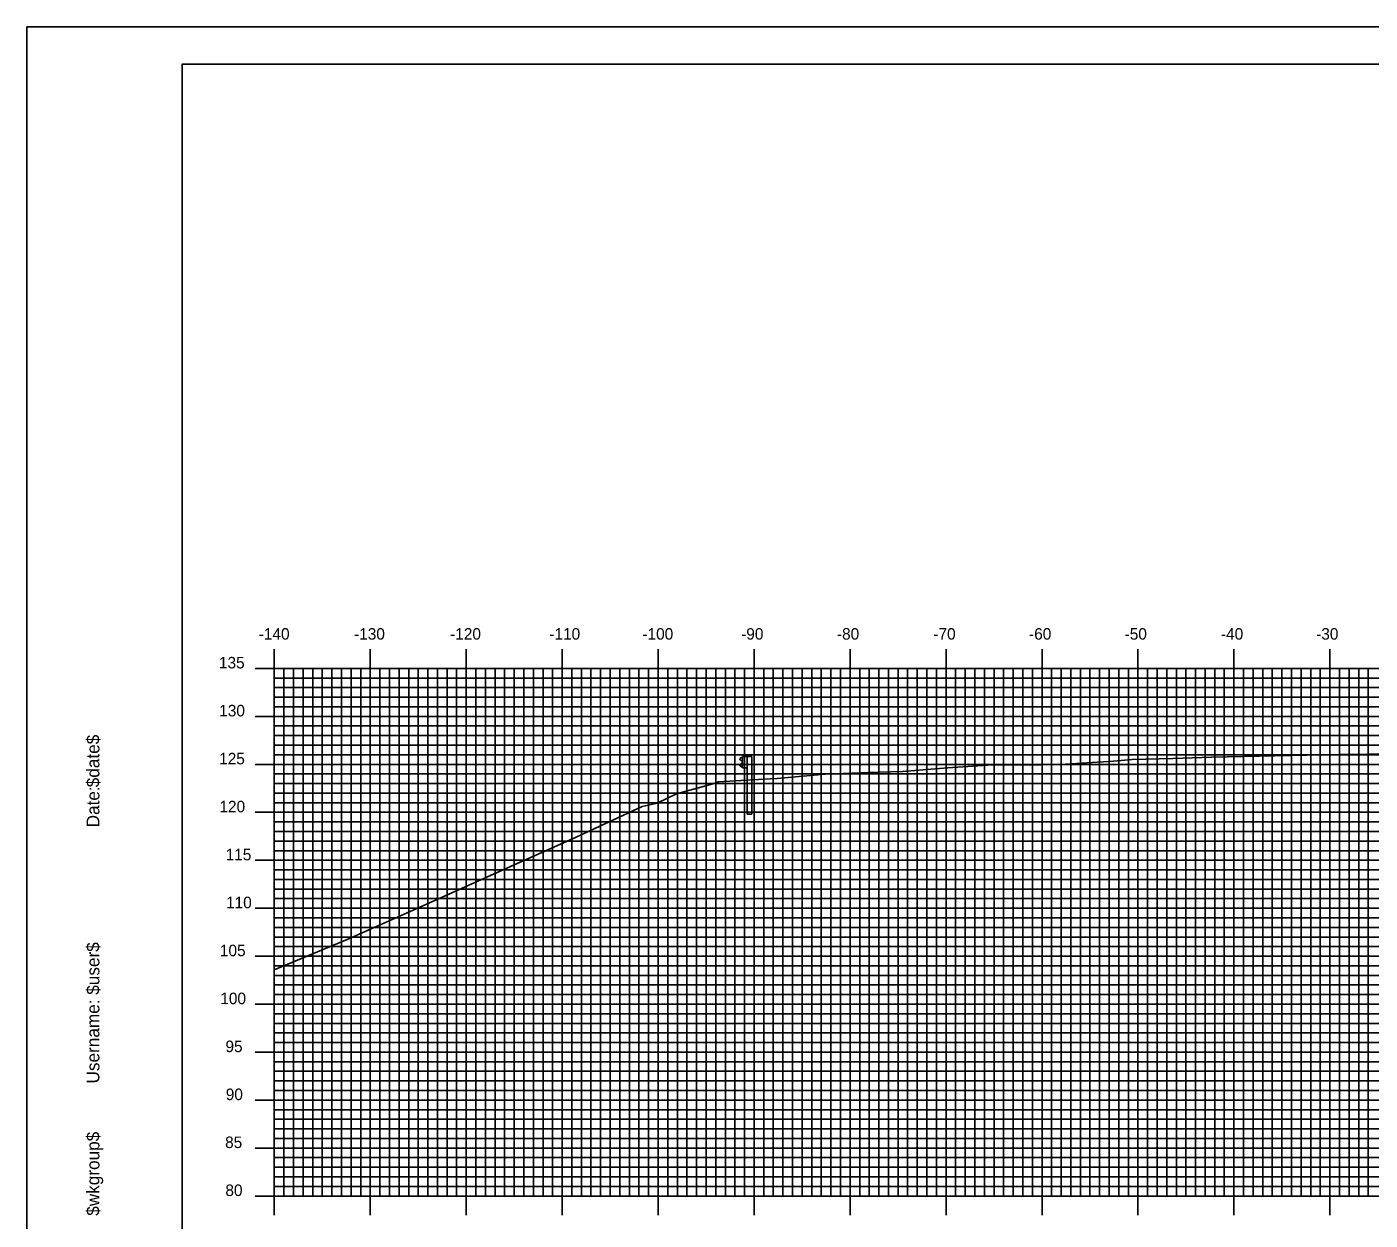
# Model space of a CAD drawing. Extents: x 857658 to 858001, y 364366 to 364586.
# Drawn here: x 857658.1 to 857798, y 364461.3 to 364585.7 of the extents above; entities that cross this region are included whole.
import ezdxf

# ---------------------------------------------------------------- set-up
doc = ezdxf.new("R2010")
doc.units = 0
for name, color, linetype in [('BORDER', 7, 'Continuous'), ('H_V ANNOTATION', 7, 'Continuous'), ('M_Roadway_Centerline', 7, 'Continuous'), ('MAJOR', 7, 'Continuous'), ('MINOR', 7, 'Continuous'), ('PLOT BOUNDARY', 7, 'Continuous'), ('S_Guardrail_Beam', 7, 'Continuous'), ('S_Roadway_Centerline', 7, 'Continuous')]:
    doc.layers.add(name, color=color, linetype=linetype)

msp = doc.modelspace()

# ---------------------------------------------------------------- linework, layer by layer
at = {"layer": 'BORDER'}
msp.add_lwpolyline([(857674.25, 364371.79), (857994.25, 364371.79), (857994.25, 364581.79), (857674.25, 364581.79)], close=True, dxfattribs=at)
at = {"layer": 'MAJOR'}
for p, q in [((857683.85, 364520.79), (857683.85, 364518.79)), ((857693.85, 364520.79), (857693.85, 364518.79)), ((857703.85, 364520.79), (857703.85, 364518.79)), ((857713.85, 364520.79), (857713.85, 364518.79)), ((857723.85, 364520.79), (857723.85, 364518.79)), ((857733.85, 364520.79), (857733.85, 364518.79)), ((857743.85, 364520.79), (857743.85, 364518.79)), ((857753.85, 364520.79), (857753.85, 364518.79)), ((857763.85, 364520.79), (857763.85, 364518.79)), ((857773.85, 364520.79), (857773.85, 364518.79)), ((857783.85, 364520.79), (857783.85, 364518.79)), ((857793.85, 364520.79), (857793.85, 364518.79)), ((857681.84, 364518.79), (857683.85, 364518.79)), ((857683.85, 364518.79), (857963.85, 364518.79)), ((857683.85, 364463.79), (857683.85, 364518.79)), ((857683.85, 364463.79), (857683.85, 364518.79)), ((857683.85, 364518.79), (857963.85, 364518.79)), ((857693.85, 364463.79), (857693.85, 364518.79)), ((857703.85, 364463.79), (857703.85, 364518.79)), ((857713.85, 364463.79), (857713.85, 364518.79)), ((857723.85, 364463.79), (857723.85, 364518.79)), ((857733.85, 364463.79), (857733.85, 364518.79)), ((857743.85, 364463.79), (857743.85, 364518.79)), ((857753.85, 364463.79), (857753.85, 364518.79)), ((857763.85, 364463.79), (857763.85, 364518.79)), ((857773.85, 364463.79), (857773.85, 364518.79)), ((857783.85, 364463.79), (857783.85, 364518.79)), ((857793.85, 364463.79), (857793.85, 364518.79)), ((857681.84, 364513.79), (857683.85, 364513.79)), ((857683.85, 364513.79), (857963.85, 364513.79)), ((857681.84, 364508.79), (857683.85, 364508.79)), ((857683.85, 364508.79), (857963.85, 364508.79)), ((857681.84, 364503.79), (857683.85, 364503.79)), ((857683.85, 364503.79), (857963.85, 364503.79)), ((857681.84, 364498.79), (857683.85, 364498.79)), ((857683.85, 364498.79), (857963.85, 364498.79)), ((857681.84, 364493.79), (857683.85, 364493.79)), ((857683.85, 364493.79), (857963.85, 364493.79)), ((857681.84, 364488.79), (857683.85, 364488.79)), ((857683.85, 364488.79), (857963.85, 364488.79)), ((857681.84, 364483.79), (857683.85, 364483.79)), ((857683.85, 364483.79), (857963.85, 364483.79)), ((857681.84, 364478.79), (857683.85, 364478.79)), ((857683.85, 364478.79), (857963.85, 364478.79)), ((857681.84, 364473.79), (857683.85, 364473.79)), ((857683.85, 364473.79), (857963.85, 364473.79)), ((857681.84, 364468.79), (857683.85, 364468.79)), ((857683.85, 364468.79), (857963.85, 364468.79)), ((857681.84, 364463.79), (857683.85, 364463.79)), ((857683.85, 364463.79), (857963.85, 364463.79)), ((857683.85, 364463.79), (857963.85, 364463.79)), ((857683.85, 364461.78), (857683.85, 364463.79)), ((857693.85, 364461.78), (857693.85, 364463.79)), ((857703.85, 364461.78), (857703.85, 364463.79)), ((857713.85, 364461.78), (857713.85, 364463.79)), ((857723.85, 364461.78), (857723.85, 364463.79)), ((857733.85, 364461.78), (857733.85, 364463.79)), ((857743.85, 364461.78), (857743.85, 364463.79)), ((857753.85, 364461.78), (857753.85, 364463.79)), ((857763.85, 364461.78), (857763.85, 364463.79)), ((857773.85, 364461.78), (857773.85, 364463.79)), ((857783.85, 364461.78), (857783.85, 364463.79)), ((857793.85, 364461.78), (857793.85, 364463.79))]:
    msp.add_line(p, q, dxfattribs=at)
at = {"layer": 'MINOR'}
for p, q in [((857683.85, 364517.79), (857963.85, 364517.79)), ((857683.85, 364517.79), (857685.85, 364517.79)), ((857684.85, 364463.79), (857684.85, 364518.79)), ((857685.85, 364463.79), (857685.85, 364518.79)), ((857686.85, 364463.79), (857686.85, 364518.79)), ((857687.85, 364463.79), (857687.85, 364518.79)), ((857688.85, 364463.79), (857688.85, 364518.79)), ((857689.85, 364463.79), (857689.85, 364518.79)), ((857690.85, 364463.79), (857690.85, 364518.79)), ((857691.85, 364463.79), (857691.85, 364518.79)), ((857692.85, 364463.79), (857692.85, 364518.79)), ((857694.85, 364463.79), (857694.85, 364518.79)), ((857695.85, 364463.79), (857695.85, 364518.79)), ((857696.85, 364463.79), (857696.85, 364518.79)), ((857697.85, 364463.79), (857697.85, 364518.79)), ((857698.85, 364463.79), (857698.85, 364518.79)), ((857699.85, 364463.79), (857699.85, 364518.79)), ((857700.85, 364463.79), (857700.85, 364518.79)), ((857701.85, 364463.79), (857701.85, 364518.79)), ((857702.85, 364463.79), (857702.85, 364518.79)), ((857704.85, 364463.79), (857704.85, 364518.79)), ((857705.85, 364463.79), (857705.85, 364518.79)), ((857706.85, 364463.79), (857706.85, 364518.79)), ((857707.85, 364463.79), (857707.85, 364518.79)), ((857708.85, 364463.79), (857708.85, 364518.79)), ((857709.85, 364463.79), (857709.85, 364518.79)), ((857710.85, 364463.79), (857710.85, 364518.79)), ((857711.85, 364463.79), (857711.85, 364518.79)), ((857712.85, 364463.79), (857712.85, 364518.79)), ((857714.85, 364463.79), (857714.85, 364518.79)), ((857715.85, 364463.79), (857715.85, 364518.79)), ((857716.85, 364463.79), (857716.85, 364518.79)), ((857717.85, 364463.79), (857717.85, 364518.79)), ((857718.85, 364463.79), (857718.85, 364518.79)), ((857719.85, 364463.79), (857719.85, 364518.79)), ((857720.85, 364463.79), (857720.85, 364518.79)), ((857721.85, 364463.79), (857721.85, 364518.79)), ((857722.85, 364463.79), (857722.85, 364518.79)), ((857724.85, 364463.79), (857724.85, 364518.79)), ((857725.85, 364463.79), (857725.85, 364518.79)), ((857726.85, 364463.79), (857726.85, 364518.79)), ((857727.85, 364463.79), (857727.85, 364518.79)), ((857728.85, 364463.79), (857728.85, 364518.79)), ((857729.85, 364463.79), (857729.85, 364518.79)), ((857730.85, 364463.79), (857730.85, 364518.79)), ((857731.85, 364463.79), (857731.85, 364518.79)), ((857732.85, 364463.79), (857732.85, 364518.79)), ((857734.85, 364463.79), (857734.85, 364518.79)), ((857735.85, 364463.79), (857735.85, 364518.79)), ((857736.85, 364463.79), (857736.85, 364518.79)), ((857737.85, 364463.79), (857737.85, 364518.79)), ((857738.85, 364463.79), (857738.85, 364518.79)), ((857739.85, 364463.79), (857739.85, 364518.79)), ((857740.85, 364463.79), (857740.85, 364518.79)), ((857741.85, 364463.79), (857741.85, 364518.79)), ((857742.85, 364463.79), (857742.85, 364518.79)), ((857744.85, 364463.79), (857744.85, 364518.79)), ((857745.85, 364463.79), (857745.85, 364518.79)), ((857746.85, 364463.79), (857746.85, 364518.79)), ((857747.85, 364463.79), (857747.85, 364518.79)), ((857748.85, 364463.79), (857748.85, 364518.79)), ((857749.85, 364463.79), (857749.85, 364518.79)), ((857750.85, 364463.79), (857750.85, 364518.79)), ((857751.85, 364463.79), (857751.85, 364518.79)), ((857752.85, 364463.79), (857752.85, 364518.79)), ((857754.85, 364463.79), (857754.85, 364518.79)), ((857755.85, 364463.79), (857755.85, 364518.79)), ((857756.85, 364463.79), (857756.85, 364518.79)), ((857757.85, 364463.79), (857757.85, 364518.79)), ((857758.85, 364463.79), (857758.85, 364518.79)), ((857759.85, 364463.79), (857759.85, 364518.79)), ((857760.85, 364463.79), (857760.85, 364518.79)), ((857761.85, 364463.79), (857761.85, 364518.79)), ((857762.85, 364463.79), (857762.85, 364518.79)), ((857764.85, 364463.79), (857764.85, 364518.79)), ((857765.85, 364463.79), (857765.85, 364518.79)), ((857766.85, 364463.79), (857766.85, 364518.79)), ((857767.85, 364463.79), (857767.85, 364518.79)), ((857768.85, 364463.79), (857768.85, 364518.79)), ((857769.85, 364463.79), (857769.85, 364518.79)), ((857770.85, 364463.79), (857770.85, 364518.79)), ((857771.85, 364463.79), (857771.85, 364518.79)), ((857772.85, 364463.79), (857772.85, 364518.79)), ((857774.85, 364463.79), (857774.85, 364518.79)), ((857775.85, 364463.79), (857775.85, 364518.79)), ((857776.85, 364463.79), (857776.85, 364518.79)), ((857777.85, 364463.79), (857777.85, 364518.79)), ((857778.85, 364463.79), (857778.85, 364518.79)), ((857779.85, 364463.79), (857779.85, 364518.79)), ((857780.85, 364463.79), (857780.85, 364518.79)), ((857781.85, 364463.79), (857781.85, 364518.79)), ((857782.85, 364463.79), (857782.85, 364518.79)), ((857784.85, 364463.79), (857784.85, 364518.79)), ((857785.85, 364463.79), (857785.85, 364518.79)), ((857786.85, 364463.79), (857786.85, 364518.79)), ((857787.85, 364463.79), (857787.85, 364518.79)), ((857788.85, 364463.79), (857788.85, 364518.79)), ((857789.85, 364463.79), (857789.85, 364518.79)), ((857790.85, 364463.79), (857790.85, 364518.79)), ((857791.85, 364463.79), (857791.85, 364518.79)), ((857792.85, 364463.79), (857792.85, 364518.79)), ((857794.85, 364463.79), (857794.85, 364518.79)), ((857795.85, 364463.79), (857795.85, 364518.79)), ((857796.85, 364463.79), (857796.85, 364518.79)), ((857797.85, 364463.79), (857797.85, 364518.79)), ((857683.85, 364516.79), (857963.85, 364516.79)), ((857683.85, 364516.79), (857685.85, 364516.79)), ((857683.85, 364515.79), (857963.85, 364515.79)), ((857683.85, 364515.79), (857685.85, 364515.79)), ((857683.85, 364514.79), (857963.85, 364514.79)), ((857683.85, 364514.79), (857685.85, 364514.79)), ((857683.85, 364512.79), (857963.85, 364512.79)), ((857683.85, 364512.79), (857685.85, 364512.79)), ((857683.85, 364511.79), (857963.85, 364511.79)), ((857683.85, 364511.79), (857685.85, 364511.79)), ((857683.85, 364510.79), (857963.85, 364510.79)), ((857683.85, 364510.79), (857685.85, 364510.79)), ((857683.85, 364509.79), (857963.85, 364509.79)), ((857683.85, 364509.79), (857685.85, 364509.79)), ((857683.85, 364507.79), (857963.85, 364507.79)), ((857683.85, 364507.79), (857685.85, 364507.79)), ((857683.85, 364506.79), (857963.85, 364506.79)), ((857683.85, 364506.79), (857685.85, 364506.79)), ((857683.85, 364505.79), (857963.85, 364505.79)), ((857683.85, 364505.79), (857685.85, 364505.79)), ((857683.85, 364504.79), (857963.85, 364504.79)), ((857683.85, 364504.79), (857685.85, 364504.79)), ((857683.85, 364502.79), (857963.85, 364502.79)), ((857683.85, 364502.79), (857685.85, 364502.79)), ((857683.85, 364501.79), (857963.85, 364501.79)), ((857683.85, 364501.79), (857685.85, 364501.79)), ((857683.85, 364500.79), (857963.85, 364500.79)), ((857683.85, 364500.79), (857685.85, 364500.79)), ((857683.85, 364499.79), (857963.85, 364499.79)), ((857683.85, 364499.79), (857685.85, 364499.79)), ((857683.85, 364497.79), (857963.85, 364497.79)), ((857683.85, 364497.79), (857685.85, 364497.79)), ((857683.85, 364496.79), (857963.85, 364496.79)), ((857683.85, 364496.79), (857685.85, 364496.79)), ((857683.85, 364495.79), (857963.85, 364495.79)), ((857683.85, 364495.79), (857685.85, 364495.79)), ((857683.85, 364494.79), (857963.85, 364494.79)), ((857683.85, 364494.79), (857685.85, 364494.79)), ((857683.85, 364492.79), (857963.85, 364492.79)), ((857683.85, 364492.79), (857685.85, 364492.79)), ((857683.85, 364491.79), (857963.85, 364491.79)), ((857683.85, 364491.79), (857685.85, 364491.79)), ((857683.85, 364490.79), (857963.85, 364490.79)), ((857683.85, 364490.79), (857685.85, 364490.79)), ((857683.85, 364489.79), (857963.85, 364489.79)), ((857683.85, 364489.79), (857685.85, 364489.79)), ((857683.85, 364487.79), (857963.85, 364487.79)), ((857683.85, 364487.79), (857685.85, 364487.79)), ((857683.85, 364486.79), (857963.85, 364486.79)), ((857683.85, 364486.79), (857685.85, 364486.79)), ((857683.85, 364485.79), (857963.85, 364485.79)), ((857683.85, 364485.79), (857685.85, 364485.79)), ((857683.85, 364484.79), (857963.85, 364484.79)), ((857683.85, 364484.79), (857685.85, 364484.79)), ((857683.85, 364482.79), (857963.85, 364482.79)), ((857683.85, 364482.79), (857685.85, 364482.79)), ((857683.85, 364481.79), (857963.85, 364481.79)), ((857683.85, 364481.79), (857685.85, 364481.79)), ((857683.85, 364480.79), (857963.85, 364480.79)), ((857683.85, 364480.79), (857685.85, 364480.79)), ((857683.85, 364479.79), (857963.85, 364479.79)), ((857683.85, 364479.79), (857685.85, 364479.79)), ((857683.85, 364477.79), (857963.85, 364477.79)), ((857683.85, 364477.79), (857685.85, 364477.79)), ((857683.85, 364476.79), (857963.85, 364476.79)), ((857683.85, 364476.79), (857685.85, 364476.79)), ((857683.85, 364475.79), (857963.85, 364475.79)), ((857683.85, 364475.79), (857685.85, 364475.79)), ((857683.85, 364474.79), (857963.85, 364474.79)), ((857683.85, 364474.79), (857685.85, 364474.79)), ((857683.85, 364472.79), (857963.85, 364472.79)), ((857683.85, 364472.79), (857685.85, 364472.79)), ((857683.85, 364471.79), (857963.85, 364471.79)), ((857683.85, 364471.79), (857685.85, 364471.79)), ((857683.85, 364470.79), (857963.85, 364470.79)), ((857683.85, 364470.79), (857685.85, 364470.79)), ((857683.85, 364469.79), (857963.85, 364469.79)), ((857683.85, 364469.79), (857685.85, 364469.79)), ((857683.85, 364467.79), (857963.85, 364467.79)), ((857683.85, 364467.79), (857685.85, 364467.79)), ((857683.85, 364466.79), (857963.85, 364466.79)), ((857683.85, 364466.79), (857685.85, 364466.79)), ((857683.85, 364465.79), (857963.85, 364465.79)), ((857683.85, 364465.79), (857685.85, 364465.79)), ((857683.85, 364464.79), (857963.85, 364464.79)), ((857683.85, 364464.79), (857685.85, 364464.79))]:
    msp.add_line(p, q, dxfattribs=at)
at = {"layer": 'PLOT BOUNDARY'}
msp.add_lwpolyline([(857658.06, 364365.67), (857998.06, 364365.67), (857998.06, 364585.67), (857658.06, 364585.67)], close=True, dxfattribs=at)
at = {"layer": 'S_Guardrail_Beam'}
for p, q in [((857732.54, 364509.51), (857732.39, 364509.41)), ((857732.54, 364509.51), (857732.39, 364509.41)), ((857732.64, 364509.54), (857732.55, 364509.52)), ((857732.64, 364509.54), (857732.55, 364509.52)), ((857732.64, 364509.61), (857733.13, 364509.61)), ((857732.64, 364508.44), (857732.64, 364509.61)), ((857732.64, 364509.61), (857733.13, 364509.61)), ((857732.64, 364508.44), (857732.64, 364509.61)), ((857733.13, 364509.61), (857733.62, 364509.61)), ((857733.13, 364509.61), (857733.13, 364508.44)), ((857733.13, 364509.61), (857733.62, 364509.61)), ((857733.13, 364509.61), (857733.13, 364508.44)), ((857733.62, 364509.61), (857733.62, 364503.61)), ((857733.62, 364509.61), (857733.62, 364503.61)), ((857732.39, 364509.27), (857732.59, 364509.13)), ((857732.39, 364509.27), (857732.59, 364509.13)), ((857732.59, 364508.91), (857732.39, 364508.78)), ((857732.59, 364508.91), (857732.39, 364508.78)), ((857732.39, 364508.64), (857732.54, 364508.54)), ((857732.39, 364508.64), (857732.54, 364508.54)), ((857732.55, 364508.53), (857732.64, 364508.51)), ((857732.55, 364508.53), (857732.64, 364508.51)), ((857732.62, 364509.07), (857732.62, 364508.98)), ((857732.62, 364509.07), (857732.62, 364508.98)), ((857733.13, 364508.44), (857732.64, 364508.44)), ((857733.13, 364508.44), (857732.64, 364508.44)), ((857733.13, 364503.61), (857733.13, 364508.44)), ((857733.13, 364503.61), (857733.13, 364508.44)), ((857733.13, 364503.61), (857733.62, 364503.61)), ((857733.13, 364503.61), (857733.62, 364503.61))]:
    msp.add_line(p, q, dxfattribs=at)
for centre, major_axis, start_param, end_param in [((857732.44, 364509.34), (-0.0877, 0), 5.323254, 7.243116), ((857732.44, 364509.34), (-0.0877, 0), 5.323254, 7.243116), ((857732.56, 364509.48), (-0.0417, 0), 4.886922, 5.323254), ((857732.56, 364509.48), (-0.0417, 0), 4.886922, 5.323254), ((857732.44, 364508.71), (-0.0877, 0), 5.323254, 7.243116), ((857732.44, 364508.71), (-0.0877, 0), 5.323254, 7.243116), ((857732.56, 364508.57), (-0.0417, 0), 0.959931, 1.396263), ((857732.56, 364508.57), (-0.0417, 0), 0.959931, 1.396263), ((857732.54, 364509.07), (0.0789, 0), 0, 0.959931), ((857732.54, 364509.07), (0.0789, 0), 0, 0.959931), ((857732.54, 364508.98), (0.0789, 0), 5.323254, 6.283185), ((857732.54, 364508.98), (0.0789, 0), 5.323254, 6.283185)]:
    msp.add_ellipse(centre, major_axis=major_axis, ratio=0.995501, start_param=start_param, end_param=end_param, dxfattribs=at)
at = {"layer": 'S_Roadway_Centerline'}
msp.add_lwpolyline([(857683.85, 364487.36), (857691.43, 364490.54), (857698.94, 364493.87), (857709.48, 364498.58), (857715.31, 364501.19), (857722.2, 364504.4), (857723.73, 364504.76), (857725.84, 364505.74), (857726.39, 364505.89), (857728.67, 364506.53), (857729.7, 364506.81), (857730.12, 364506.97), (857735.52, 364507.29), (857736.25, 364507.33), (857741.26, 364507.76), (857746.87, 364507.97), (857749.3, 364508.06), (857752.31, 364508.28), (857754.05, 364508.41), (857758.2, 364508.71), (857760.04, 364508.73), (857762.63, 364508.71), (857764.88, 364508.76), (857766.31, 364508.81), (857768.01, 364508.92), (857769.61, 364509), (857770.91, 364509.1), (857773.25, 364509.3), (857777.5, 364509.41), (857781.51, 364509.53), (857789.78, 364509.71), (857794.81, 364509.8), (857797.93, 364509.86), (857799.51, 364509.88)], dxfattribs=at)

# ---------------------------------------------------------------- texts
at = {"layer": 'BORDER'}
for s, p in [('$date$', (857665.62, 364506.4)), ('Date:', (857665.62, 364502.22)), ('$user$', (857665.62, 364484.77)), ('Username:', (857665.62, 364475.52)), ('$wkgroup$', (857665.62, 364461.73))]:
    msp.add_text(s, height=1.339, rotation=90, dxfattribs=at).set_placement(p)
at = {"layer": 'H_V ANNOTATION'}
for s, p in [('-140', (857682.23, 364521.79)), ('-130', (857692.16, 364521.79)), ('-120', (857702.17, 364521.79)), ('-110', (857712.51, 364521.79)), ('-100', (857722.21, 364521.79)), ('-90', (857732.5, 364521.79)), ('-80', (857742.48, 364521.79)), ('-70', (857752.53, 364521.79)), ('-60', (857762.5, 364521.79)), ('-50', (857772.46, 364521.79)), ('-40', (857782.5, 364521.79)), ('-30', (857792.42, 364521.79)), ('135', (857678.08, 364518.79)), ('130', (857678.11, 364513.79)), ('125', (857678.1, 364508.79)), ('120', (857678.13, 364503.79)), ('115', (857678.78, 364498.79)), ('110', (857678.82, 364493.79)), ('105', (857678.18, 364488.79)), ('100', (857678.22, 364483.79)), ('95', (857678.76, 364478.79)), ('90', (857678.79, 364473.79)), ('85', (857678.72, 364468.79)), ('80', (857678.75, 364463.79))]:
    msp.add_text(s, height=1.2, dxfattribs=at).set_placement(p)
at = {"layer": 'M_Roadway_Centerline'}
for s, p in [('C', (857749.3, 364508.06)), ('L', (857749.3, 364508.05))]:
    msp.add_text(s, height=0.0146, dxfattribs=at).set_placement(p)
at = {"layer": 'MAJOR'}
msp.add_text('-', height=0.012, dxfattribs=at).set_placement((857683.84, 364463.79))

doc.saveas('drawing.dxf')
